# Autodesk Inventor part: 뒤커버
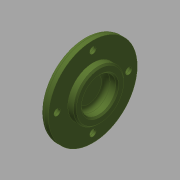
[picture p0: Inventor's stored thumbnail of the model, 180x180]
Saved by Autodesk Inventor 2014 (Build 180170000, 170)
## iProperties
Created: 2015-12
Part Number: 뒤커버
Document SubType Name: Modeling
Designer: mdu
Density: 2.71 g/cm^3
Material: 알루미늄 6061
Appearance: 알루미늄 - 평지
Mass: 56.2003 g
Surface Area: 84.0408 cm^2
Volume: 20.7381 cm^3
Author: mdu
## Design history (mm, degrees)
sketch "스케치1"
  geometry: L1 (-7, 0)-(7, 0); L2 (-7, 0)-(-7, 15.539); L3 (-7, 15.539)-(-4, 18.5); L4 (-4, 18.5)-(-4, 31); L5 (-4, 31)-(2, 31); L6 (2, 31)-(2, 17.5); L7 (2, 17.5)-(7, 17.5); L8 (7, 17.5)-(7, 0); 2 further points
  constraints: 16 end point, 4 parallel, 2 perpendicular, 1 coincident, 1 horizontal, 1 midpoint
  dimensions: "d0" = 14 distance of L1.start L1.end; "d1" = 62 diameter of L5 L1; "d2" = 35 diameter of L7 L1; "d3" = 37 diameter of L3.end L1; "d4" = 3 distance between parallel lines of L4 L2; "d5" = 6 distance of L4.end L5.end
revolve "회전1" sketch "스케치1" stored, may be unused: angle "d6" = 90 deg
sketch "스케치2" dims "d32" = 50
  geometry: 3 further points
  constraints: 2 vertical alignment, 1 coincident, 2 other
hole "구멍1" sketch "스케치2" at (0, 25) diameter "d8" = 4.5; stored, may be unused: countersink angle "d12" = 90 deg, drill point angle "d14" = 118 deg; dims "d9" = 6, "d10" = 8, "d11" = 4.4, "d13" = 8
hole "구멍2" diameter "d20" = 24; stored, may be unused: countersink angle "d24" = 90 deg, drill point angle "d26" = 0 deg; dims "d18" = 10, "d19" = 10, "d21" = 6, "d22" = 8, "d23" = 4.4, "d25" = 8
fillet "모깎기1" dims "d27" = 3
fillet "모깎기2" dims "d28" = 3
chamfer "모따기1" distance "d29" = 1; stored, may be unused: second distance "d30" = 2, angle "d31" = 45 deg
node "솔리드1"
pattern_circular "원형 패턴1" dims angle "d16" = 360 deg
